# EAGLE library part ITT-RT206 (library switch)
ROTARY SWITCH ITT-Cannon
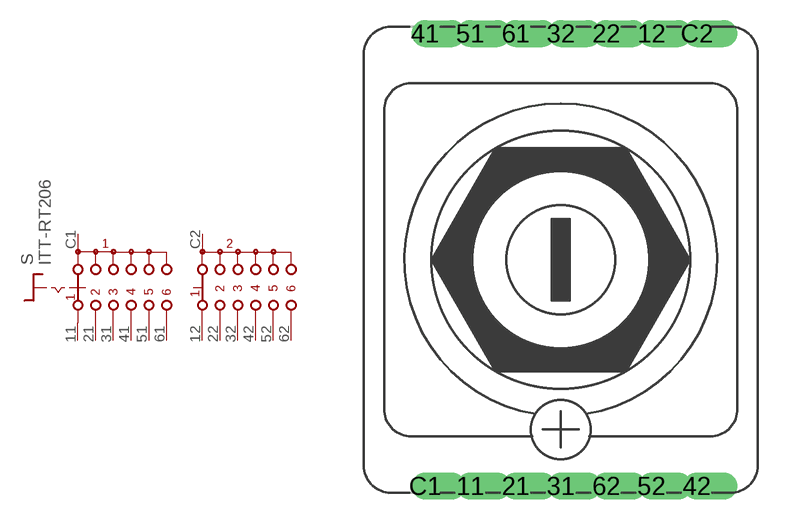
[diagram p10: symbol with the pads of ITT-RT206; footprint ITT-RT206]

Designator prefix S

## ITT-RT206  [ITT-RT206]
11  11  pas
12  12  pas
21  21  pas
22  22  pas
31  31  pas
32  32  pas
41  41  pas
42  42  pas
51  51  pas
52  52  pas
61  61  pas
62  62  pas
C1  C1  pas
C2  C2  pas

## Footprint ITT-RT206 (pad centres in mm)
ROTARY SWITCH ITT-Cannon
drill 1.016 offset: 11 -5.08,-12.7; 12 5.08,12.7; 21 -2.54,-12.7; 22 2.54,12.7; 31 0,-12.7; 32 0,12.7; 41 -7.62,12.7; 42 7.62,-12.7; 51 -5.08,12.7; 52 5.08,-12.7; 61 -2.54,12.7; 62 2.54,-12.7; C1 -7.62,-12.7; C2 7.62,12.7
